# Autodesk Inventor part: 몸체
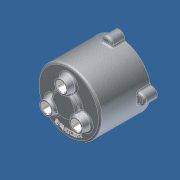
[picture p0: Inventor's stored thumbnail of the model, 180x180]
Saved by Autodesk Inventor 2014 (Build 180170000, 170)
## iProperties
Created: 2012-05
Part Number: 몸체
Document SubType Name: 모델링
Designer: SeoGD™
Material: 일반
Appearance: 기본값
Mass: 175.482 g
Surface Area: 687.659 cm^2
Volume: 175.482 cm^3
Density: 1 g/cm^3
변환 표준: STEP AP214IS
파일 이름: C:\Users\SeoGD\Desktop\?쒗뿕\紐몄껜.stp
전처리기: Build: 253, Release: 2010 SP1 - Date: Wed 07/29/2009
전송 단위: 밀리미터
불확실성: 0.01
Author: SeoGD™
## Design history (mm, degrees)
sketch "스케치2"
  geometry: C1 r 50 at (0, 0); 1 further point
  constraints: 1 centre point, 1 coincident
  dimensions: "d9" = 100 diameter of C1
extrude "돌출2" new body sketch "스케치2" distance "d10" = 80; taper "d11" = 0 deg
feature "쉘1" dims "d12" = 5
sketch "스케치3" dims "d13" = 55
  geometry: C1 r 7.5 at (0, 27.5); C2 r 12.5 at (0, 27.5); 2 further points
  constraints: 2 centre point, 2 coincident, 2 vertical alignment, 2 other
  dimensions: "d14" = 15 diameter of C1; "d15" = 25 diameter of C2
extrude "돌출3" join sketch "스케치3" distance "d16" = 12; taper "d17" = -10 deg
hole "구멍2" diameter "d20" = 15; stored, may be unused: countersink angle "d24" = 90 deg, drill point angle "d26" = 118 deg; dims "d18" = 10, "d19" = 10, "d21" = 6, "d22" = 4, "d23" = 2, "d25" = 15
chamfer "모따기1" distance "d27" = 1; stored, may be unused: second distance "d28" = 2, angle "d29" = 45 deg
sketch "스케치4"
  geometry: L1 (0, 0)-(0, 88); L2 (0, 70)-(13.16, 70); L3 (-45, 75)-(45, 75) reference; L4 (-50, 80)-(50, 80) reference; L5 (13.16, 70)-(14.5, 75); L6 (20, 80)-(20, 88); L7 (20, 88)-(0, 88); L8 (20, 80)-(14.5, 75)
  constraints: 12 end point, 3 point on line, 2 perpendicular, 1 vertical
  dimensions: "d34" = 40 diameter of L6 L1; "d35" = 105 deg angle of L5 L3; "d36" = 5 distance between parallel lines of L2 L3; "d37" = 8 distance between parallel lines of L7 L4; "d51" = 29 diameter of L5.end L1
revolve "회전1" sketch "스케치4" stored, may be unused: angle "d38" = 90 deg
hole "구멍3" diameter "d41" = 15; stored, may be unused: countersink angle "d45" = 90 deg, drill point angle "d47" = 0 deg; dims "d39" = 10, "d40" = 10, "d42" = 6, "d43" = 22, "d44" = 13, "d46" = 15
chamfer "모따기2" distance "d48" = 1; stored, may be unused: second distance "d49" = 2, angle "d50" = 45 deg
fillet "모깎기1" dims "d52" = 3
fillet "모깎기2" dims "d53" = 3, "d72" = 0.2
sketch "스케치5"
  geometry: A1 r 50 centre (0, 0) between (50, 0) and (-8.074, 49.344) reference; A2 r 8.5 centre (0, 52) between (8.074, 49.344) and (-8.074, 49.344); 1 further point
  constraints: 5 point on circle, 1 centre point, 1 horizontal alignment
  dimensions: "d54" = 90 deg dimension on point (0, 0) A2.centre A1.start; "d55" = 52 distance of A2.centre point (0, 0); "d56" = 17 diameter of A2
extrude "돌출4" join sketch "스케치5" distance "d57" = 20; taper "d58" = 0 deg
fillet "모깎기3" dims "d59" = 3
hole "구멍4" diameter "d62" = 4.134; stored, may be unused: countersink angle "d66" = 90 deg, drill point angle "d68" = 118 deg; dims "d60" = 10, "d61" = 10, "d63" = 12, "d64" = 22, "d65" = 13, "d67" = 15
sketch "스케치6"
  geometry: C1 r 47 at (0, 0) reference; C2 r 42.5 at (0, 0); 1 further point
  constraints: 1 centre point, 1 coincident, 1 other
  dimensions: "d73" = 85 diameter of C2
feature "엠보싱1" sketch "스케치6" dims "d74" = 1, "d75" = 0
node "솔리드1"
node "솔리드 본체"
node "곡면 본체"
pattern_circular "원형 패턴1" dims "d31" = 360 deg
pattern_circular "원형 패턴2" dims "d70" = 360 deg
node "솔리드2"
